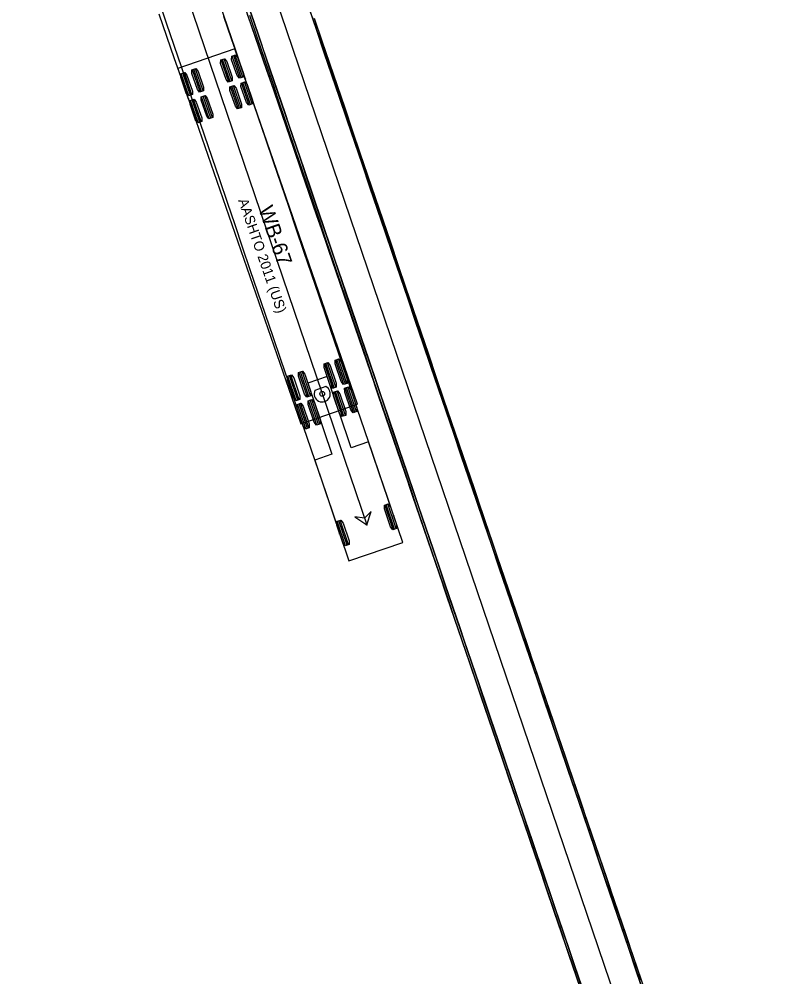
# Model space of a CAD drawing. Extents: x 916040 to 917457, y 328936 to 330267.
# Drawn here: x 916815.8 to 916922.6, y 329072.6 to 329207.6 of the extents above; entities that cross this region are included whole.
import ezdxf

# ---------------------------------------------------------------- set-up
doc = ezdxf.new("R2010")
doc.units = 0
for name, color, linetype in [('EB_RightontoSaco_WB67_v2', 7, 'Continuous'), ('NB_LeftontoRoute25_WB67', 7, 'Continuous'), ('NB_RightontoRoute25_WB67', 7, 'Continuous'), ('NB_ThruontoManchester_WB67', 7, 'Continuous')]:
    doc.layers.add(name, color=color, linetype=linetype)

msp = doc.modelspace()

# ---------------------------------------------------------------- linework, layer by layer
at = {"layer": 'EB_RightontoSaco_WB67_v2'}
for p, q in [((916815.82, 329280.44), (916864.81, 329136.29)), ((916846.21, 329203.39), (916838.18, 329200.61)), ((916863.53, 329153.3), (916846.21, 329203.39)), ((916845.36, 329198.71), (916844.28, 329201.82)), ((916845.58, 329198.78), (916844.5, 329201.9)), ((916845.79, 329198.86), (916844.71, 329201.97)), ((916846.92, 329199.24), (916845.84, 329202.36)), ((916847.13, 329199.32), (916846.06, 329202.44)), ((916847.35, 329199.39), (916846.27, 329202.51)), ((916838.18, 329200.61), (916855.5, 329150.52)), ((916841.31, 329197.31), (916840.23, 329200.42)), ((916841.53, 329197.38), (916840.45, 329200.5)), ((916841.74, 329197.46), (916840.66, 329200.57)), ((916839.75, 329196.77), (916838.67, 329199.88)), ((916839.97, 329196.84), (916838.89, 329199.96)), ((916840.18, 329196.92), (916839.11, 329200.03)), ((916848.66, 329195.61), (916847.58, 329198.73)), ((916846.67, 329194.92), (916845.59, 329198.04)), ((916846.88, 329195), (916845.8, 329198.12)), ((916847.1, 329195.07), (916846.02, 329198.19)), ((916848.23, 329195.46), (916847.15, 329198.58)), ((916848.44, 329195.54), (916847.36, 329198.66)), ((916841.06, 329192.99), (916839.98, 329196.1)), ((916841.27, 329193.06), (916840.2, 329196.18)), ((916841.49, 329193.14), (916840.41, 329196.25)), ((916842.62, 329193.53), (916841.54, 329196.64)), ((916842.83, 329193.6), (916841.76, 329196.72)), ((916843.05, 329193.67), (916841.97, 329196.79)), ((916861.8, 329156.14), (916860.62, 329159.61)), ((916862.02, 329156.21), (916860.84, 329159.69)), ((916860.02, 329155.54), (916858.84, 329159.01)), ((916860.24, 329155.61), (916859.06, 329159.08)), ((916860.46, 329155.68), (916859.28, 329159.15)), ((916861.59, 329156.07), (916860.41, 329159.54)), ((916854.88, 329153.79), (916853.7, 329157.26)), ((916855.1, 329153.86), (916853.92, 329157.33)), ((916855.31, 329153.93), (916854.13, 329157.41)), ((916856.44, 329154.32), (916855.26, 329157.79)), ((916856.66, 329154.39), (916855.48, 329157.86)), ((916856.88, 329154.47), (916855.7, 329157.94)), ((916859.22, 329157.2), (916856.5, 329156.27)), ((916862.63, 329147.16), (916859.22, 329157.2)), ((916856.5, 329156.27), (916859.91, 329146.24)), ((916859.04, 329155.77), (916857.51, 329155.25)), ((916862.94, 329152.09), (916861.76, 329155.56)), ((916863.15, 329152.16), (916861.97, 329155.64)), ((916863.37, 329152.24), (916862.19, 329155.71)), ((916861.38, 329151.56), (916860.2, 329155.03)), ((916861.59, 329151.63), (916860.41, 329155.1)), ((916861.81, 329151.71), (916860.63, 329155.18)), ((916856.23, 329149.81), (916855.05, 329153.28)), ((916856.45, 329149.88), (916855.27, 329153.36)), ((916856.66, 329149.96), (916855.48, 329153.43)), ((916855.5, 329150.52), (916863.53, 329153.3)), ((916857.79, 329150.34), (916856.61, 329153.81)), ((916858.01, 329150.42), (916856.83, 329153.89)), ((916858.23, 329150.49), (916857.05, 329153.96)), ((916863.53, 329153.3), (916863.53, 329153.3)), ((916865.06, 329147.99), (916862.63, 329147.16)), ((916869.89, 329133.79), (916865.06, 329147.99)), ((916859.91, 329146.24), (916857.48, 329145.41)), ((916857.48, 329145.41), (916862.31, 329131.21)), ((916868.54, 329135.62), (916867.36, 329139.09)), ((916868.75, 329135.69), (916867.57, 329139.16)), ((916868.97, 329135.76), (916867.79, 329139.23)), ((916861.83, 329133.34), (916860.65, 329136.81)), ((916862.05, 329133.41), (916860.87, 329136.88)), ((916862.26, 329133.48), (916861.08, 329136.95)), ((916862.31, 329131.21), (916869.89, 329133.79)), ((916869.89, 329133.79), (916869.89, 329133.79))]:
    msp.add_line(p, q, dxfattribs=at)
for points in [[(916835.45, 329210.24), (916836.53, 329207.07), (916837.6, 329203.91), (916838.68, 329200.75), (916839.75, 329197.59), (916840.82, 329194.43), (916841.9, 329191.27), (916842.97, 329188.11), (916844.05, 329184.95), (916845.12, 329181.79), (916846.2, 329178.62), (916847.27, 329175.46), (916848.34, 329172.3), (916849.42, 329169.14), (916850.49, 329165.98), (916851.57, 329162.82), (916852.64, 329159.66), (916853.72, 329156.49), (916854.79, 329153.33), (916855.87, 329150.17), (916856.94, 329147.01), (916858.01, 329143.85), (916859.09, 329140.69), (916860.16, 329137.53), (916861.02, 329135)], [(916844.1, 329209.65), (916845.17, 329206.49), (916846.25, 329203.33), (916847.32, 329200.17), (916848.4, 329197.01), (916849.47, 329193.85), (916850.55, 329190.68), (916851.62, 329187.52), (916852.7, 329184.36), (916853.77, 329181.2), (916854.84, 329178.04), (916855.92, 329174.88), (916856.99, 329171.72), (916858.07, 329168.55), (916859.14, 329165.39), (916860.22, 329162.23), (916861.29, 329159.07), (916862.37, 329155.91), (916863.44, 329152.75), (916864.51, 329149.59), (916865.59, 329146.42), (916866.66, 329143.26), (916867.74, 329140.1), (916868.6, 329137.57)], [(916835.5, 329208.34), (916836.59, 329205.19), (916837.68, 329202.04), (916838.78, 329198.88), (916839.65, 329196.36)], [(916844.62, 329207.98), (916845.71, 329204.82), (916846.81, 329201.66), (916847.68, 329199.14)]]:
    msp.add_lwpolyline(points, dxfattribs=at)
for points in [[(916845.85, 329198.87), (916845.3, 329198.69), (916844.99, 329199.07), (916844.21, 329201.31), (916844.23, 329201.81), (916844.77, 329201.99), (916845.08, 329201.61), (916845.86, 329199.37)], [(916847.4, 329199.41), (916846.86, 329199.23), (916846.55, 329199.61), (916845.77, 329201.85), (916845.79, 329202.34), (916846.33, 329202.53), (916846.64, 329202.15), (916847.42, 329199.91)], [(916841.8, 329197.47), (916841.26, 329197.29), (916840.94, 329197.67), (916840.17, 329199.91), (916840.18, 329200.41), (916840.72, 329200.59), (916841.03, 329200.21), (916841.81, 329197.97)], [(916840.24, 329196.93), (916839.7, 329196.75), (916839.38, 329197.13), (916838.61, 329199.37), (916838.62, 329199.87), (916839.16, 329200.05), (916839.47, 329199.67), (916840.25, 329197.43)], [(916848.71, 329195.63), (916848.17, 329195.45), (916847.86, 329195.83), (916847.08, 329198.07), (916847.09, 329198.56), (916847.63, 329198.75), (916847.95, 329198.37), (916848.72, 329196.13)], [(916847.15, 329195.09), (916846.61, 329194.91), (916846.3, 329195.29), (916845.52, 329197.53), (916845.53, 329198.03), (916846.07, 329198.21), (916846.39, 329197.83), (916847.16, 329195.59)], [(916841.55, 329193.15), (916841, 329192.97), (916840.69, 329193.35), (916839.91, 329195.59), (916839.93, 329196.09), (916840.47, 329196.27), (916840.78, 329195.89), (916841.56, 329193.65)], [(916843.1, 329193.69), (916842.56, 329193.51), (916842.25, 329193.89), (916841.47, 329196.13), (916841.49, 329196.63), (916842.03, 329196.81), (916842.34, 329196.43), (916843.12, 329194.19)], [(916862.07, 329156.23), (916861.53, 329156.05), (916861.2, 329156.48), (916860.35, 329158.98), (916860.35, 329159.52), (916860.89, 329159.7), (916861.22, 329159.27), (916862.07, 329156.77)], [(916860.51, 329155.7), (916859.97, 329155.52), (916859.64, 329155.95), (916858.79, 329158.45), (916858.79, 329158.99), (916859.33, 329159.17), (916859.66, 329158.74), (916860.51, 329156.24)], [(916855.37, 329153.95), (916854.83, 329153.77), (916854.5, 329154.2), (916853.65, 329156.7), (916853.65, 329157.24), (916854.19, 329157.42), (916854.52, 329156.99), (916855.36, 329154.49)], [(916856.93, 329154.48), (916856.39, 329154.3), (916856.06, 329154.73), (916855.21, 329157.23), (916855.21, 329157.77), (916855.75, 329157.96), (916856.08, 329157.52), (916856.93, 329155.03)], [(916863.43, 329152.26), (916862.88, 329152.07), (916862.56, 329152.5), (916861.71, 329155), (916861.7, 329155.54), (916862.25, 329155.73), (916862.57, 329155.3), (916863.42, 329152.8)], [(916861.86, 329151.72), (916861.32, 329151.54), (916860.99, 329151.97), (916860.14, 329154.47), (916860.14, 329155.01), (916860.68, 329155.2), (916861.01, 329154.77), (916861.86, 329152.27)], [(916856.72, 329149.98), (916856.18, 329149.79), (916855.85, 329150.22), (916855, 329152.72), (916855, 329153.26), (916855.54, 329153.45), (916855.87, 329153.02), (916856.72, 329150.52)], [(916858.28, 329150.51), (916857.74, 329150.32), (916857.41, 329150.75), (916856.56, 329153.25), (916856.56, 329153.79), (916857.1, 329153.98), (916857.43, 329153.55), (916858.28, 329151.05)], [(916864.81, 329136.29), (916865.45, 329138.18), (916864.49, 329137.23), (916863.15, 329137.4)], [(916869.02, 329135.78), (916868.48, 329135.6), (916868.15, 329136.03), (916867.31, 329138.53), (916867.3, 329139.07), (916867.84, 329139.25), (916868.17, 329138.82), (916869.02, 329136.32)], [(916862.32, 329133.5), (916861.78, 329133.32), (916861.45, 329133.75), (916860.6, 329136.25), (916860.6, 329136.79), (916861.14, 329136.97), (916861.47, 329136.54), (916862.32, 329134.04)]]:
    msp.add_lwpolyline(points, close=True, dxfattribs=at)
for centre, radius in [((916847.68, 329199.14), 0.0417), ((916839.65, 329196.36), 0.0417), ((916858.54, 329154.75), 0.34), ((916868.6, 329137.57), 0.0417), ((916864.81, 329136.29), 0.0417), ((916861.02, 329135), 0.0417)]:
    msp.add_circle(centre, radius, dxfattribs=at)
msp.add_arc((916858.54, 329154.75), 1.14, 153.7724, 63.7724, dxfattribs=at)
at = {"layer": 'NB_LeftontoRoute25_WB67'}
msp.add_line((916922.62, 329002.7), (916826.94, 329284.22), dxfattribs=at)
for points in [[(916847.93, 329210.03), (916849.01, 329206.87), (916850.08, 329203.72), (916851.15, 329200.56), (916852.22, 329197.4), (916853.3, 329194.25), (916854.37, 329191.09), (916855.44, 329187.94), (916856.51, 329184.78), (916857.59, 329181.62), (916858.66, 329178.47), (916859.73, 329175.31), (916860.8, 329172.16), (916861.88, 329169), (916862.95, 329165.84), (916864.02, 329162.69), (916865.1, 329159.53), (916866.17, 329156.37), (916867.24, 329153.22), (916868.31, 329150.06), (916869.39, 329146.91), (916870.46, 329143.75), (916871.53, 329140.59), (916872.6, 329137.44), (916873.68, 329134.28), (916874.75, 329131.13), (916875.82, 329127.97), (916876.9, 329124.81), (916877.97, 329121.66), (916879.04, 329118.5), (916880.11, 329115.34), (916881.19, 329112.19), (916882.26, 329109.03), (916883.33, 329105.88), (916884.4, 329102.72), (916885.48, 329099.56), (916886.55, 329096.41), (916887.62, 329093.25), (916888.69, 329090.1), (916889.77, 329086.94), (916890.84, 329083.78), (916891.91, 329080.63), (916892.99, 329077.47), (916894.06, 329074.31), (916895.13, 329071.16)], [(916847.97, 329208.25), (916849.07, 329205.1), (916850.15, 329201.96), (916851.24, 329198.81), (916852.33, 329195.66), (916853.42, 329192.51), (916854.5, 329189.36), (916855.59, 329186.21), (916856.67, 329183.05), (916857.75, 329179.9), (916858.84, 329176.75), (916859.92, 329173.6), (916861, 329170.45), (916862.08, 329167.29), (916863.16, 329164.14), (916864.24, 329160.99), (916865.32, 329157.83), (916866.39, 329154.68), (916867.47, 329151.53), (916868.55, 329148.37), (916869.63, 329145.22), (916870.7, 329142.06), (916871.78, 329138.91), (916872.86, 329135.76), (916873.93, 329132.6), (916875.01, 329129.45), (916876.08, 329126.29), (916877.16, 329123.14), (916878.23, 329119.98), (916879.31, 329116.83), (916880.38, 329113.67), (916881.46, 329110.52), (916882.53, 329107.36), (916883.61, 329104.21), (916884.68, 329101.05), (916885.76, 329097.89), (916886.83, 329094.74), (916887.9, 329091.58), (916888.98, 329088.43), (916890.05, 329085.27), (916891.13, 329082.12), (916892.2, 329078.96), (916893.27, 329075.8), (916894.35, 329072.65), (916895.42, 329069.49)], [(916856.58, 329209.45), (916857.65, 329206.29), (916858.72, 329203.14), (916859.8, 329199.98), (916860.87, 329196.82), (916861.94, 329193.67), (916863.02, 329190.51), (916864.09, 329187.35), (916865.16, 329184.2), (916866.23, 329181.04), (916867.31, 329177.89), (916868.38, 329174.73), (916869.45, 329171.57), (916870.52, 329168.42), (916871.6, 329165.26), (916872.67, 329162.11), (916873.74, 329158.95), (916874.82, 329155.79), (916875.89, 329152.64), (916876.96, 329149.48), (916878.03, 329146.32), (916879.11, 329143.17), (916880.18, 329140.01), (916881.25, 329136.86), (916882.32, 329133.7), (916883.4, 329130.54), (916884.47, 329127.39), (916885.54, 329124.23), (916886.61, 329121.08), (916887.69, 329117.92), (916888.76, 329114.76), (916889.83, 329111.61), (916890.91, 329108.45), (916891.98, 329105.29), (916893.05, 329102.14), (916894.12, 329098.98), (916895.2, 329095.83), (916896.27, 329092.67), (916897.34, 329089.51), (916898.41, 329086.36), (916899.49, 329083.2), (916900.56, 329080.05), (916901.63, 329076.89), (916902.71, 329073.73), (916903.78, 329070.58)], [(916857.1, 329207.89), (916858.19, 329204.73), (916859.28, 329201.58), (916860.37, 329198.43), (916861.45, 329195.28), (916862.54, 329192.12), (916863.62, 329188.97), (916864.71, 329185.82), (916865.79, 329182.66), (916866.87, 329179.51), (916867.96, 329176.36), (916869.04, 329173.2), (916870.12, 329170.05), (916871.2, 329166.89), (916872.28, 329163.74), (916873.36, 329160.58), (916874.44, 329157.43), (916875.51, 329154.28), (916876.59, 329151.12), (916877.67, 329147.97), (916878.75, 329144.81), (916879.82, 329141.66), (916880.9, 329138.5), (916881.98, 329135.34), (916883.05, 329132.19), (916884.13, 329129.03), (916885.2, 329125.88), (916886.28, 329122.72), (916887.36, 329119.57), (916888.43, 329116.41), (916889.51, 329113.26), (916890.58, 329110.1), (916891.65, 329106.94), (916892.73, 329103.79), (916893.8, 329100.63), (916894.88, 329097.48), (916895.95, 329094.32), (916897.03, 329091.17), (916898.1, 329088.01), (916899.17, 329084.85), (916900.25, 329081.7), (916901.32, 329078.54), (916902.39, 329075.39), (916903.47, 329072.23)]]:
    msp.add_lwpolyline(points, dxfattribs=at)
at = {"layer": 'NB_RightontoRoute25_WB67'}
msp.add_line((916922.62, 329002.7), (916826.94, 329284.22), dxfattribs=at)
for points in [[(916895.24, 329070.84), (916894.17, 329074), (916893.09, 329077.16), (916892.02, 329080.31), (916890.95, 329083.47), (916889.87, 329086.62), (916888.8, 329089.78), (916887.73, 329092.94), (916886.66, 329096.09), (916885.58, 329099.25), (916884.51, 329102.4), (916883.44, 329105.56), (916882.37, 329108.72), (916881.29, 329111.87), (916880.22, 329115.03), (916879.15, 329118.19), (916878.07, 329121.34), (916877, 329124.5), (916875.93, 329127.65), (916874.86, 329130.81), (916873.78, 329133.97), (916872.71, 329137.12), (916871.64, 329140.28), (916870.57, 329143.43), (916869.49, 329146.59), (916868.42, 329149.75), (916867.35, 329152.9), (916866.28, 329156.06), (916865.2, 329159.22), (916864.13, 329162.37), (916863.06, 329165.53), (916861.98, 329168.68), (916860.91, 329171.84), (916859.84, 329175), (916858.77, 329178.15), (916857.69, 329181.31), (916856.62, 329184.46), (916855.55, 329187.62), (916854.48, 329190.78), (916853.4, 329193.93), (916852.33, 329197.09), (916851.26, 329200.25), (916850.19, 329203.4), (916849.11, 329206.56), (916848.04, 329209.71)], [(916903.89, 329070.26), (916902.81, 329073.42), (916901.74, 329076.57), (916900.67, 329079.73), (916899.59, 329082.89), (916898.52, 329086.04), (916897.45, 329089.2), (916896.38, 329092.35), (916895.3, 329095.51), (916894.23, 329098.67), (916893.16, 329101.82), (916892.09, 329104.98), (916891.01, 329108.14), (916889.94, 329111.29), (916888.87, 329114.45), (916887.79, 329117.6), (916886.72, 329120.76), (916885.65, 329123.92), (916884.58, 329127.07), (916883.5, 329130.23), (916882.43, 329133.38), (916881.36, 329136.54), (916880.29, 329139.7), (916879.21, 329142.85), (916878.14, 329146.01), (916877.07, 329149.17), (916876, 329152.32), (916874.92, 329155.48), (916873.85, 329158.63), (916872.78, 329161.79), (916871.7, 329164.95), (916870.63, 329168.1), (916869.56, 329171.26), (916868.49, 329174.41), (916867.41, 329177.57), (916866.34, 329180.73), (916865.27, 329183.88), (916864.2, 329187.04), (916863.12, 329190.19), (916862.05, 329193.35), (916860.98, 329196.51), (916859.9, 329199.66), (916858.83, 329202.82), (916857.76, 329205.98), (916856.69, 329209.13)], [(916894.46, 329072.34), (916893.39, 329075.5), (916892.32, 329078.66), (916891.25, 329081.81), (916890.17, 329084.97), (916889.1, 329088.12), (916888.03, 329091.28), (916886.96, 329094.44), (916885.88, 329097.59), (916884.81, 329100.75), (916883.74, 329103.9), (916882.66, 329107.06), (916881.59, 329110.22), (916880.52, 329113.37), (916879.45, 329116.53), (916878.37, 329119.69), (916877.3, 329122.84), (916876.23, 329126), (916875.16, 329129.15), (916874.08, 329132.31), (916873.01, 329135.47), (916871.94, 329138.62), (916870.87, 329141.78), (916869.79, 329144.93), (916868.72, 329148.09), (916867.65, 329151.25), (916866.57, 329154.4), (916865.5, 329157.56), (916864.43, 329160.72), (916863.36, 329163.87), (916862.28, 329167.03), (916861.21, 329170.18), (916860.14, 329173.34), (916859.07, 329176.5), (916857.99, 329179.65), (916856.92, 329182.81), (916855.85, 329185.96), (916854.77, 329189.12), (916853.7, 329192.28), (916852.63, 329195.43), (916851.56, 329198.59), (916850.48, 329201.75), (916849.41, 329204.9), (916848.34, 329208.06)], [(916903.58, 329071.92), (916902.51, 329075.08), (916901.44, 329078.23), (916900.37, 329081.39), (916899.29, 329084.55), (916898.22, 329087.7), (916897.15, 329090.86), (916896.08, 329094.02), (916895, 329097.17), (916893.93, 329100.33), (916892.86, 329103.48), (916891.79, 329106.64), (916890.71, 329109.8), (916889.64, 329112.95), (916888.57, 329116.11), (916887.49, 329119.26), (916886.42, 329122.42), (916885.35, 329125.58), (916884.28, 329128.73), (916883.2, 329131.89), (916882.13, 329135.05), (916881.06, 329138.2), (916879.99, 329141.36), (916878.91, 329144.51), (916877.84, 329147.67), (916876.77, 329150.83), (916875.69, 329153.98), (916874.62, 329157.14), (916873.55, 329160.29), (916872.48, 329163.45), (916871.4, 329166.61), (916870.33, 329169.76), (916869.26, 329172.92), (916868.19, 329176.07), (916867.11, 329179.23), (916866.04, 329182.39), (916864.97, 329185.54), (916863.9, 329188.7), (916862.82, 329191.86), (916861.75, 329195.01), (916860.68, 329198.17), (916859.6, 329201.32), (916858.53, 329204.48), (916857.46, 329207.64)]]:
    msp.add_lwpolyline(points, dxfattribs=at)
at = {"layer": 'NB_ThruontoManchester_WB67'}
msp.add_line((916922.62, 329002.7), (916826.94, 329284.22), dxfattribs=at)
for points in [[(916847.43, 329209.83), (916848.52, 329206.68), (916849.61, 329203.53), (916850.7, 329200.38), (916851.79, 329197.23), (916852.87, 329194.08), (916853.96, 329190.93), (916855.04, 329187.78), (916856.13, 329184.63), (916857.21, 329181.48), (916858.29, 329178.33), (916859.38, 329175.17), (916860.46, 329172.02), (916861.54, 329168.87), (916862.62, 329165.72), (916863.7, 329162.56), (916864.78, 329159.41), (916865.85, 329156.26), (916866.93, 329153.1), (916868.01, 329149.95), (916869.09, 329146.8), (916870.16, 329143.64), (916871.24, 329140.49), (916872.32, 329137.33), (916873.39, 329134.18), (916874.47, 329131.02), (916875.55, 329127.87), (916876.62, 329124.71), (916877.7, 329121.56), (916878.77, 329118.4), (916879.85, 329115.25), (916880.92, 329112.09), (916882, 329108.94), (916883.07, 329105.78), (916884.15, 329102.63), (916885.22, 329099.47), (916886.29, 329096.32), (916887.37, 329093.16), (916888.44, 329090.01), (916889.52, 329086.85), (916890.59, 329083.69), (916891.66, 329080.54), (916892.74, 329077.38), (916893.81, 329074.23), (916894.88, 329071.07)], [(916848.47, 329208.45), (916849.54, 329205.29), (916850.61, 329202.14), (916851.69, 329198.98), (916852.76, 329195.83), (916853.83, 329192.67), (916854.91, 329189.51), (916855.98, 329186.36), (916857.05, 329183.2), (916858.12, 329180.05), (916859.2, 329176.89), (916860.27, 329173.73), (916861.34, 329170.58), (916862.41, 329167.42), (916863.49, 329164.26), (916864.56, 329161.11), (916865.63, 329157.95), (916866.7, 329154.8), (916867.78, 329151.64), (916868.85, 329148.48), (916869.92, 329145.33), (916871, 329142.17), (916872.07, 329139.02), (916873.14, 329135.86), (916874.21, 329132.7), (916875.29, 329129.55), (916876.36, 329126.39), (916877.43, 329123.24), (916878.5, 329120.08), (916879.58, 329116.92), (916880.65, 329113.77), (916881.72, 329110.61), (916882.79, 329107.45), (916883.87, 329104.3), (916884.94, 329101.14), (916886.01, 329097.99), (916887.09, 329094.83), (916888.16, 329091.67), (916889.23, 329088.52), (916890.3, 329085.36), (916891.38, 329082.21), (916892.45, 329079.05), (916893.52, 329075.89), (916894.59, 329072.74), (916895.67, 329069.58)], [(916856.55, 329209.46), (916857.64, 329206.31), (916858.73, 329203.16), (916859.82, 329200.01), (916860.91, 329196.85), (916862, 329193.7), (916863.08, 329190.55), (916864.17, 329187.39), (916865.25, 329184.24), (916866.33, 329181.09), (916867.42, 329177.93), (916868.5, 329174.78), (916869.58, 329171.63), (916870.66, 329168.47), (916871.74, 329165.32), (916872.82, 329162.16), (916873.9, 329159.01), (916874.98, 329155.85), (916876.05, 329152.7), (916877.13, 329149.54), (916878.21, 329146.39), (916879.29, 329143.23), (916880.36, 329140.08), (916881.44, 329136.92), (916882.52, 329133.77), (916883.59, 329130.61), (916884.67, 329127.46), (916885.74, 329124.3), (916886.82, 329121.15), (916887.89, 329117.99), (916888.97, 329114.83), (916890.04, 329111.68), (916891.12, 329108.52), (916892.19, 329105.37), (916893.27, 329102.21), (916894.34, 329099.06), (916895.41, 329095.9), (916896.49, 329092.74), (916897.56, 329089.59), (916898.64, 329086.43), (916899.71, 329083.28), (916900.78, 329080.12), (916901.86, 329076.96), (916902.93, 329073.81), (916904, 329070.65)], [(916857.12, 329207.87), (916858.19, 329204.71), (916859.26, 329201.56), (916860.33, 329198.4), (916861.41, 329195.25), (916862.48, 329192.09), (916863.55, 329188.93), (916864.62, 329185.78), (916865.7, 329182.62), (916866.77, 329179.46), (916867.84, 329176.31), (916868.92, 329173.15), (916869.99, 329170), (916871.06, 329166.84), (916872.13, 329163.68), (916873.21, 329160.53), (916874.28, 329157.37), (916875.35, 329154.21), (916876.42, 329151.06), (916877.5, 329147.9), (916878.57, 329144.75), (916879.64, 329141.59), (916880.72, 329138.43), (916881.79, 329135.28), (916882.86, 329132.12), (916883.93, 329128.97), (916885.01, 329125.81), (916886.08, 329122.65), (916887.15, 329119.5), (916888.22, 329116.34), (916889.3, 329113.18), (916890.37, 329110.03), (916891.44, 329106.87), (916892.51, 329103.72), (916893.59, 329100.56), (916894.66, 329097.4), (916895.73, 329094.25), (916896.81, 329091.09), (916897.88, 329087.94), (916898.95, 329084.78), (916900.02, 329081.62), (916901.1, 329078.47), (916902.17, 329075.31), (916903.24, 329072.16)]]:
    msp.add_lwpolyline(points, dxfattribs=at)

# ---------------------------------------------------------------- texts
at = {"layer": 'EB_RightontoSaco_WB67_v2'}
for s, height, p in [('AASHTO 2011 (US)', 1.4167, (916846.67, 329182.02)), ('WB-67', 2.125, (916849.52, 329180.83))]:
    msp.add_text(s, height=height, rotation=289.0754, dxfattribs=at).set_placement(p)

doc.saveas('drawing.dxf')
